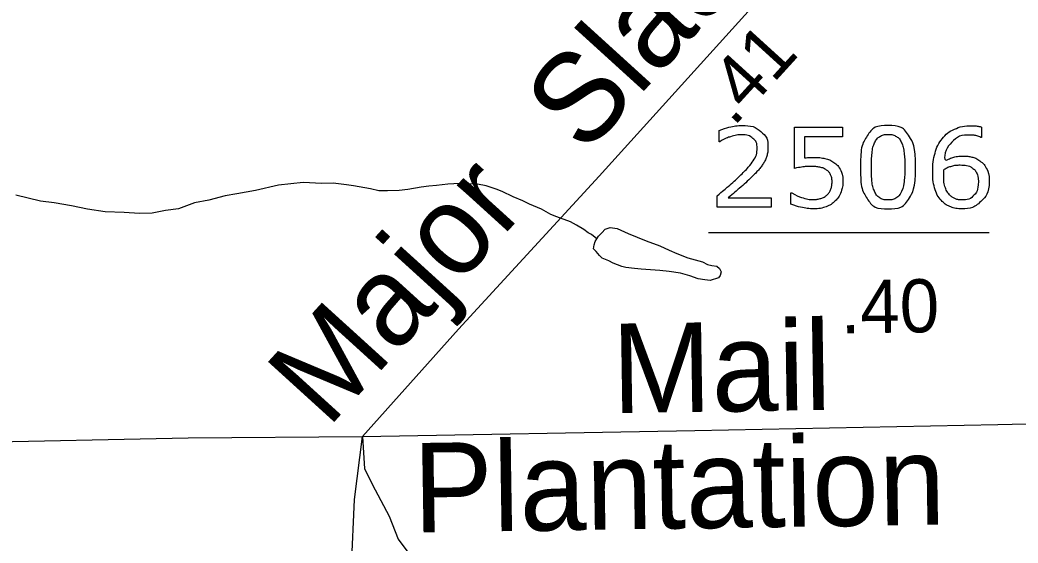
# Model space of a CAD drawing. Extents: x 2169602 to 2449496, y 721995 to 810662.
# Drawn here: x 2170042.4 to 2170098.1, y 724766 to 724795.2 of the extents above; entities that cross this region are included whole.
import ezdxf

# ---------------------------------------------------------------- set-up
doc = ezdxf.new("R2010")
doc.units = 0
doc.layers.add('Old_Level_1', color=7, linetype='Continuous')

msp = doc.modelspace()

# ---------------------------------------------------------------- linework, layer by layer
at = {"layer": 'Old_Level_1'}
msp.add_line((2170080.841, 724783.324), (2170096.521, 724783.324), dxfattribs=at)
for points in [[(2170095.664, 724810.099), (2170092.257, 724806.391), (2170085.691, 724798.626), (2170074.725, 724786.482), (2170066.866, 724777.922), (2170061.495, 724771.924)], [(2170085.632, 724786.911), (2170085.632, 724789.206), (2170088.313, 724789.206), (2170088.313, 724788.682), (2170086.207, 724788.682), (2170086.207, 724787.498)], [(2170096.088, 724789.221), (2170096.088, 724788.646), (2170096.058, 724788.646)], [(2170081.46, 724788.395), (2170081.43, 724788.395), (2170081.43, 724789.023)], [(2170074.598, 724782.978), (2170074.301, 724783.216), (2170074.116, 724783.301), (2170073.872, 724783.492), (2170073.448, 724783.73), (2170073.117, 724783.915), (2170072.357, 724784.194), (2170072.025, 724784.34), (2170071.499, 724784.623), (2170070.827, 724784.907), (2170070.451, 724785.09), (2170069.925, 724785.324), (2170069.296, 724785.611), (2170068.97, 724785.748), (2170068.405, 724785.939), (2170067.922, 724786.031), (2170066.928, 724786.065), (2170066.265, 724786.022), (2170065.641, 724785.962), (2170065.208, 724785.921), (2170064.784, 724785.869), (2170064.033, 724785.722), (2170063.551, 724785.671), (2170062.893, 724785.663), (2170062.415, 724785.659), (2170061.938, 724785.76), (2170060.992, 724785.941), (2170060.612, 724785.989), (2170059.852, 724786.075), (2170059.233, 724786.073), (2170058.181, 724786.115), (2170056.802, 724785.968), (2170055.52, 724785.67), (2170054.482, 724785.481), (2170053.814, 724785.378), (2170052.918, 724785.138), (2170052.104, 724784.991), (2170051.212, 724784.653), (2170050.496, 724784.55), (2170049.735, 724784.405), (2170049.029, 724784.396), (2170048.176, 724784.438), (2170047.123, 724784.482), (2170046.124, 724784.623), (2170045.228, 724784.807), (2170044.268, 724784.99), (2170043.507, 724785.086), (2170042.123, 724785.41)], [(2170084.34, 724784.75), (2170081.321, 724784.75), (2170081.321, 724785.38)], [(2170085.44, 724784.916), (2170085.44, 724785.547), (2170085.481, 724785.547)], [(2170081.941, 724785.267), (2170084.34, 724785.267), (2170084.34, 724784.75)], [(2170074.598, 724782.978), (2170074.691, 724783.118), (2170074.876, 724783.312), (2170075.066, 724783.505), (2170075.344, 724783.597), (2170075.734, 724783.548), (2170076.353, 724783.272), (2170077.352, 724782.85), (2170078.117, 724782.571), (2170078.638, 724782.329), (2170079.062, 724782.149), (2170079.681, 724781.911), (2170080.49, 724781.682), (2170080.782, 724781.542), (2170081.016, 724781.487), (2170081.299, 724781.444), (2170081.45, 724781.306), (2170081.538, 724781.119), (2170081.494, 724780.923), (2170081.401, 724780.783), (2170080.934, 724780.632), (2170080.636, 724780.677), (2170080.251, 724780.726), (2170079.788, 724780.911), (2170079.267, 724781.057), (2170078.643, 724781.142), (2170078.117, 724781.192), (2170077.6, 724781.233), (2170077.074, 724781.284), (2170076.694, 724781.321), (2170076.216, 724781.364), (2170075.982, 724781.419), (2170075.51, 724781.607), (2170075.271, 724781.749), (2170074.891, 724781.883), (2170074.74, 724782.03), (2170074.55, 724782.263), (2170074.413, 724782.408), (2170074.452, 724782.643), (2170074.501, 724782.828), (2170074.598, 724782.978)], [(2170061.495, 724771.924), (2170080.071, 724772.248), (2170097.006, 724772.596), (2170108.197, 724772.845), (2170109.988, 724773.392)], [(2170008.166, 724770.483), (2170008.65, 724770.53), (2170018.001, 724771.078), (2170029.191, 724771.476), (2170039.238, 724771.576), (2170051.759, 724771.849), (2170061.495, 724771.924)], [(2170060.738, 724738.323), (2170060.377, 724746.987), (2170059.836, 724751.32), (2170059.475, 724752.583), (2170059, 724754.743), (2170058.944, 724758.519), (2170060.887, 724764.627), (2170061.053, 724768.403), (2170061.495, 724771.924)], [(2170061.495, 724771.924), (2170061.6, 724770.107), (2170062.203, 724768.942), (2170062.995, 724767.459), (2170063.495, 724766.182), (2170064.882, 724764.294), (2170066.103, 724763.683), (2170067.491, 724764.183), (2170067.491, 724761.684), (2170068.924, 724761.451), (2170072.374, 724760.401), (2170074.372, 724758.847), (2170075.26, 724757.236), (2170075.537, 724755.515), (2170075.149, 724752.016), (2170073.817, 724743.687), (2170073.659, 724739.654)]]:
    msp.add_lwpolyline(points, dxfattribs=at)
for points in [[(2170081.43, 724789.023), (2170081.643, 724789.127), (2170081.998, 724789.214), (2170082.353, 724789.301), (2170082.686, 724789.301), (2170083.372, 724789.301), (2170083.762, 724788.97), (2170084.151, 724788.64), (2170084.151, 724788.075), (2170084.151, 724787.82), (2170084.087, 724787.601), (2170084.022, 724787.381), (2170083.897, 724787.183), (2170083.78, 724786.998), (2170083.623, 724786.819), (2170083.465, 724786.639), (2170083.241, 724786.421), (2170082.92, 724786.107), (2170082.579, 724785.812), (2170082.237, 724785.518), (2170081.941, 724785.267)], [(2170092.41, 724786.981), (2170092.41, 724785.779), (2170092.035, 724785.217), (2170091.659, 724784.655), (2170090.869, 724784.655), (2170090.068, 724784.655), (2170089.698, 724785.225), (2170089.329, 724785.794), (2170089.329, 724786.975), (2170089.329, 724788.165), (2170089.703, 724788.733), (2170090.077, 724789.301), (2170090.869, 724789.301), (2170091.671, 724789.301), (2170092.041, 724788.724), (2170092.41, 724788.147), (2170092.41, 724786.981)], [(2170096.521, 724786.194), (2170096.521, 724785.514), (2170096.074, 724785.085), (2170095.626, 724784.655), (2170094.977, 724784.655), (2170094.648, 724784.655), (2170094.379, 724784.757), (2170094.109, 724784.859), (2170093.903, 724785.06), (2170093.646, 724785.308), (2170093.506, 724785.718), (2170093.367, 724786.128), (2170093.367, 724786.706), (2170093.367, 724787.299), (2170093.495, 724787.757), (2170093.622, 724788.215), (2170093.9, 724788.571), (2170094.164, 724788.91), (2170094.58, 724789.1), (2170094.996, 724789.29), (2170095.549, 724789.29), (2170095.726, 724789.29), (2170095.846, 724789.275), (2170095.966, 724789.26), (2170096.088, 724789.221)], [(2170081.321, 724785.38), (2170081.636, 724785.65), (2170081.952, 724785.919), (2170082.269, 724786.188), (2170082.542, 724786.454), (2170083.118, 724787.01), (2170083.331, 724787.338), (2170083.544, 724787.665), (2170083.544, 724788.045), (2170083.544, 724788.392), (2170083.314, 724788.588), (2170083.084, 724788.784), (2170082.673, 724788.784), (2170082.4, 724788.784), (2170082.082, 724788.688), (2170081.763, 724788.593), (2170081.46, 724788.395)], [(2170091.623, 724785.621), (2170091.728, 724785.863), (2170091.765, 724786.192), (2170091.802, 724786.52), (2170091.802, 724786.981), (2170091.802, 724787.437), (2170091.765, 724787.772), (2170091.728, 724788.108), (2170091.62, 724788.342), (2170091.515, 724788.572), (2170091.334, 724788.689), (2170091.153, 724788.806), (2170090.869, 724788.806), (2170090.588, 724788.806), (2170090.404, 724788.689), (2170090.22, 724788.572), (2170090.113, 724788.336), (2170090.011, 724788.114), (2170089.974, 724787.757), (2170089.936, 724787.401), (2170089.936, 724786.975), (2170089.936, 724786.508), (2170089.969, 724786.193), (2170090.002, 724785.878), (2170090.11, 724785.63), (2170090.208, 724785.396), (2170090.389, 724785.273), (2170090.57, 724785.15), (2170090.869, 724785.15), (2170091.151, 724785.15), (2170091.336, 724785.267), (2170091.521, 724785.384), (2170091.623, 724785.621)], [(2170096.058, 724788.646), (2170095.975, 724788.691), (2170095.806, 724788.732), (2170095.637, 724788.773), (2170095.46, 724788.773), (2170094.818, 724788.773), (2170094.435, 724788.371), (2170094.053, 724787.968), (2170093.99, 724787.283), (2170094.241, 724787.436), (2170094.484, 724787.515), (2170094.728, 724787.595), (2170095.048, 724787.595), (2170095.332, 724787.595), (2170095.548, 724787.542), (2170095.765, 724787.49), (2170095.992, 724787.331), (2170096.255, 724787.149), (2170096.388, 724786.87), (2170096.521, 724786.592), (2170096.521, 724786.194)], [(2170086.207, 724787.498), (2170086.336, 724787.51), (2170086.471, 724787.516), (2170086.605, 724787.522), (2170086.704, 724787.522), (2170087.067, 724787.522), (2170087.339, 724787.461), (2170087.612, 724787.399), (2170087.839, 724787.243), (2170088.079, 724787.079), (2170088.211, 724786.818), (2170088.342, 724786.557), (2170088.342, 724786.165)], [(2170085.481, 724785.547), (2170085.727, 724785.391), (2170086.056, 724785.281), (2170086.385, 724785.172), (2170086.702, 724785.172), (2170086.915, 724785.172), (2170087.114, 724785.232), (2170087.313, 724785.292), (2170087.469, 724785.442), (2170087.6, 724785.571), (2170087.668, 724785.751), (2170087.735, 724785.931), (2170087.735, 724786.168), (2170087.735, 724786.399), (2170087.656, 724786.558), (2170087.576, 724786.717), (2170087.436, 724786.813), (2170087.28, 724786.927), (2170087.057, 724786.973), (2170086.835, 724787.02), (2170086.559, 724787.02), (2170086.296, 724787.02), (2170086.053, 724786.984), (2170085.809, 724786.947), (2170085.632, 724786.911)], [(2170095.914, 724786.168), (2170095.914, 724786.446), (2170095.831, 724786.628), (2170095.749, 724786.81), (2170095.561, 724786.945), (2170095.424, 724787.04), (2170095.256, 724787.07), (2170095.089, 724787.1), (2170094.907, 724787.1), (2170094.653, 724787.1), (2170094.435, 724787.04), (2170094.217, 724786.98), (2170093.987, 724786.855), (2170093.981, 724786.789), (2170093.978, 724786.728), (2170093.975, 724786.667), (2170093.975, 724786.574), (2170093.975, 724786.102), (2170094.072, 724785.829), (2170094.169, 724785.555), (2170094.339, 724785.397), (2170094.477, 724785.265), (2170094.637, 724785.204), (2170094.796, 724785.143), (2170094.985, 724785.143), (2170095.418, 724785.143), (2170095.666, 724785.407), (2170095.914, 724785.672), (2170095.914, 724786.168)], [(2170088.342, 724786.165), (2170088.342, 724785.854), (2170088.229, 724785.569), (2170088.115, 724785.285), (2170087.917, 724785.09), (2170087.702, 724784.88), (2170087.404, 724784.768), (2170087.106, 724784.655), (2170086.714, 724784.655), (2170086.349, 724784.655), (2170086.011, 724784.732), (2170085.673, 724784.808), (2170085.44, 724784.916)]]:
    msp.add_open_spline(points, degree=3, dxfattribs=at)

# ---------------------------------------------------------------- texts
for s, height, rotation, p in [('Smithfield', 5, 288.1769, (2170096.216, 724812.544)), ('Slade', 5, 47.7186, (2170073.92, 724787.598)), ('.41', 2.9707, 47.7186, (2170082.224, 724789.184)), ('Major', 5, 47.7186, (2170059.55, 724772.325)), ('.40', 2.9707, 0.8697, (2170088.224, 724777.674)), ('Mail', 5, 0.8697, (2170075.47, 724773.223)), ('Plantation', 5, 0.8697, (2170064.359, 724766.55))]:
    msp.add_text(s, height=height, rotation=rotation, dxfattribs=at).set_placement(p)

doc.saveas('drawing.dxf')
